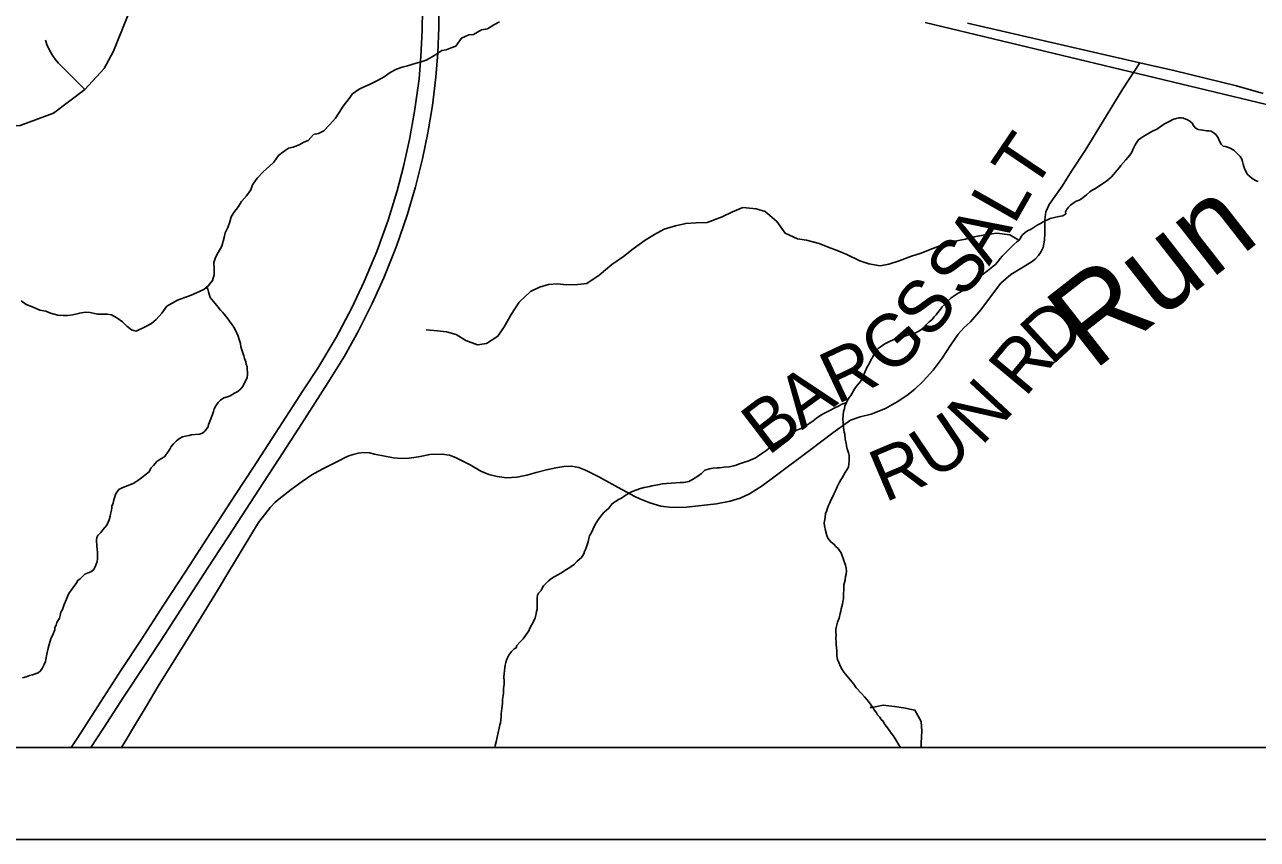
# Model space of a CAD drawing. Extents: x 44.2 to 78.2, y 4.5 to 26.5.
# Drawn here: x 50.4 to 51.74, y 18.501 to 19.388 of the extents above; entities that cross this region are included whole.
import ezdxf

# ---------------------------------------------------------------- set-up
doc = ezdxf.new("R2010")
doc.units = 0
for name, color, linetype in [('GM_X_County_Road', 7, 'Continuous'), ('GM_X_Interstate_Route', 7, 'Continuous'), ('GM_X_Minor_River', 7, 'Continuous'), ('GM_X_Minor_River_Text', 7, 'Continuous'), ('GM_X_Rail_Line', 7, 'Continuous'), ('GM_X_Township_Road', 7, 'Continuous'), ('GM_X_Township_Road_Text', 7, 'Continuous'), ('SH_Cut_Line', 7, 'Continuous'), ('SH_Data', 7, 'Continuous')]:
    doc.layers.add(name, color=color, linetype=linetype)

msp = doc.modelspace()

# ---------------------------------------------------------------- linework, layer by layer
at = {"layer": 'GM_X_County_Road'}
msp.add_lwpolyline([(51.4252, 19.3893), (51.6126, 19.3459), (51.6496, 19.3377), (51.7177, 19.3209), (51.7466, 19.3127)], dxfattribs=at)
at = {"layer": 'GM_X_Interstate_Route'}
for points in [[(50.8508, 19.4119), (50.8504, 19.3846), (50.8492, 19.3569), (50.8471, 19.3303), (50.8433, 19.2997), (50.8383, 19.27), (50.8326, 19.2416), (50.8251, 19.2113), (50.8159, 19.1802), (50.8043, 19.1467), (50.7904, 19.1122), (50.7778, 19.0841), (50.763, 19.0547), (50.7477, 19.027), (50.7297, 18.9981), (50.7013, 18.9539), (50.6765, 18.9156), (50.6541, 18.8811), (50.6273, 18.8398), (50.5992, 18.7969), (50.5752, 18.7598), (50.553, 18.7255), (50.5308, 18.6915), (50.5074, 18.6559), (50.4857, 18.6224), (50.472, 18.6014)], [(50.8327, 19.4043), (50.8323, 19.3811), (50.8309, 19.3529), (50.8288, 19.3288), (50.8239, 19.2932), (50.8185, 19.2627), (50.8119, 19.2333), (50.805, 19.2068), (50.7952, 19.175), (50.783, 19.141), (50.7691, 19.1083), (50.7557, 19.0797), (50.7385, 19.0473), (50.7187, 19.0141), (50.7024, 18.9891), (50.6767, 18.9493), (50.6489, 18.9064), (50.6292, 18.8764), (50.6025, 18.8351), (50.5751, 18.7933), (50.551, 18.7563), (50.5265, 18.7185), (50.5053, 18.686), (50.479, 18.6456), (50.4576, 18.6122), (50.4505, 18.6014)]]:
    msp.add_lwpolyline(points, dxfattribs=at)
at = {"layer": 'GM_X_Minor_River'}
for points in [[(50.7141, 19.2682), (50.7195, 19.2692), (50.7252, 19.2722), (50.7318, 19.2789), (50.738, 19.286), (50.7419, 19.292), (50.7462, 19.2988), (50.7528, 19.3074), (50.7563, 19.3123), (50.7636, 19.3175), (50.7697, 19.3204), (50.775, 19.3226), (50.7835, 19.327), (50.7907, 19.3307), (50.7973, 19.3355), (50.8042, 19.3392), (50.8103, 19.3414), (50.8164, 19.3428), (50.8255, 19.3457), (50.8312, 19.3471), (50.8366, 19.3489), (50.845, 19.3537), (50.8534, 19.3593), (50.8584, 19.3603), (50.8637, 19.3625), (50.8687, 19.3643), (50.8749, 19.3729), (50.883, 19.3766), (50.8879, 19.3769), (50.8967, 19.3821), (50.9032, 19.3831), (50.9101, 19.3875), (50.9162, 19.3905)], [(51.7415, 19.2168), (51.7385, 19.218), (51.7348, 19.2204), (51.7318, 19.2228), (51.7292, 19.2251), (51.7281, 19.2274), (51.7267, 19.2301), (51.7256, 19.2332), (51.7249, 19.2359), (51.7243, 19.2389), (51.7236, 19.2412), (51.7217, 19.2443), (51.7177, 19.2482), (51.7147, 19.2509), (51.7102, 19.2537), (51.7057, 19.2549), (51.7034, 19.2554), (51.7012, 19.2577), (51.699, 19.2616), (51.6979, 19.2646), (51.6957, 19.2677), (51.6935, 19.2697), (51.6901, 19.2717), (51.6875, 19.2721), (51.6852, 19.2722), (51.6811, 19.2727), (51.6761, 19.2736), (51.6728, 19.2755), (51.6709, 19.2779), (51.6695, 19.2806), (51.6669, 19.2825), (51.6646, 19.2841), (51.6601, 19.2857), (51.6579, 19.2862), (51.6552, 19.2862), (51.6521, 19.2856), (51.6487, 19.2845), (51.6452, 19.2827), (51.6422, 19.2813), (51.6395, 19.2798), (51.6348, 19.2765), (51.6317, 19.2743), (51.6256, 19.2715), (51.6171, 19.2664), (51.6136, 19.2642), (51.6113, 19.2624), (51.6093, 19.2597), (51.6077, 19.2568), (51.6057, 19.2534), (51.6037, 19.2481), (51.6017, 19.2455), (51.5974, 19.2407), (51.592, 19.2344), (51.59, 19.2318), (51.5818, 19.2221), (51.5763, 19.2174), (51.5636, 19.209), (51.5609, 19.2075), (51.5582, 19.2057), (51.5547, 19.2024), (51.5493, 19.198), (51.5466, 19.1965), (51.5435, 19.1955), (51.5412, 19.194), (51.5373, 19.1914), (51.535, 19.1892), (51.533, 19.1862), (51.5318, 19.184), (51.5321, 19.1817), (51.529, 19.1795), (51.5245, 19.1789), (51.5153, 19.1768), (51.5076, 19.1732), (51.5045, 19.1714), (51.5011, 19.1696), (51.4945, 19.1652), (51.4906, 19.1634), (51.4879, 19.1616), (51.4852, 19.159), (51.4833, 19.1564), (51.482, 19.1538), (51.4789, 19.1512), (51.4755, 19.1483), (51.4727, 19.1457), (51.4692, 19.142)], [(50.4656, 19.0749), (50.4713, 19.0744), (50.4793, 19.0727), (50.4895, 19.0725), (50.4944, 19.0721), (50.5, 19.0686), (50.5064, 19.0643), (50.5112, 19.0596), (50.5161, 19.0558), (50.521, 19.0541), (50.531, 19.0589), (50.5378, 19.0626), (50.5429, 19.0667), (50.549, 19.0738), (50.5545, 19.0813), (50.566, 19.088), (50.574, 19.0909), (50.5809, 19.0934), (50.5866, 19.096), (50.5946, 19.0996), (50.6, 19.1037), (50.6043, 19.1093), (50.6059, 19.1154), (50.606, 19.1211), (50.6058, 19.1287), (50.6074, 19.1344), (50.6102, 19.1396), (50.6145, 19.1468), (50.6169, 19.1559), (50.6181, 19.1612), (50.6209, 19.1668), (50.6229, 19.1732), (50.6245, 19.1785), (50.6273, 19.1834), (50.6323, 19.1898), (50.6358, 19.1954), (50.6412, 19.2014), (50.6459, 19.2078), (50.6475, 19.2135), (50.6526, 19.2206), (50.6595, 19.2277), (50.6657, 19.2333), (50.6707, 19.2381), (50.6758, 19.2453), (50.6808, 19.249), (50.6869, 19.2531), (50.6919, 19.2545), (50.6984, 19.2567), (50.7034, 19.2596), (50.7083, 19.2614), (50.7141, 19.2682), (50.7153, 19.2685)], [(51.4802, 19.1523), (51.4811, 19.1533), (51.4714, 19.1588), (51.457, 19.1606), (51.4463, 19.1593), (51.4326, 19.1569), (51.4231, 19.1544), (51.4116, 19.152), (51.3982, 19.1481), (51.3848, 19.143), (51.3749, 19.139), (51.3642, 19.1358), (51.3508, 19.1308), (51.3397, 19.1272), (51.3302, 19.1254), (51.318, 19.1276), (51.3082, 19.1308), (51.2939, 19.1376), (51.2834, 19.142), (51.2736, 19.1456), (51.2638, 19.1496), (51.2502, 19.1532), (51.2404, 19.1546), (51.2268, 19.1609), (51.218, 19.1733), (51.2053, 19.1842), (51.1955, 19.1874), (51.181, 19.1888), (51.1696, 19.1841), (51.1584, 19.1786), (51.1423, 19.1725), (51.1302, 19.1719), (51.1188, 19.1714), (51.1077, 19.1689), (51.0955, 19.165), (51.0847, 19.1595), (51.0747, 19.1532), (51.0616, 19.1436), (51.0512, 19.1354), (51.0385, 19.1266), (51.0246, 19.115), (51.0111, 19.1062), (51.0016, 19.1048), (50.989, 19.1047), (50.9792, 19.1057), (50.9696, 19.1051), (50.9597, 19.1022), (50.9501, 19.0975), (50.9377, 19.0859), (50.9291, 19.0724), (50.9212, 19.0589), (50.9146, 19.0487), (50.9022, 19.0406), (50.8923, 19.0393), (50.8795, 19.0441), (50.869, 19.0504), (50.8588, 19.0536), (50.849, 19.0546), (50.8364, 19.0556)], [(51.4692, 19.142), (51.4657, 19.1387), (51.463, 19.1357), (51.461, 19.1335), (51.4587, 19.1305), (51.4555, 19.1268), (51.4532, 19.125), (51.4505, 19.1228), (51.447, 19.1198), (51.4427, 19.1165), (51.44, 19.1143), (51.4377, 19.1121), (51.4338, 19.1092), (51.4307, 19.1066), (51.428, 19.1044), (51.4245, 19.1014), (51.4206, 19.0985), (51.4149, 19.0956), (51.4118, 19.0934), (51.4075, 19.0905), (51.4021, 19.0853), (51.4001, 19.0831), (51.3978, 19.0805), (51.3962, 19.0783), (51.3942, 19.076), (51.3911, 19.072), (51.3888, 19.0697), (51.3864, 19.0664), (51.3837, 19.0642), (51.3813, 19.062), (51.3782, 19.0586), (51.3755, 19.0564), (51.3732, 19.0546), (51.3678, 19.0521), (51.3651, 19.051), (51.3621, 19.0503), (51.3594, 19.0496), (51.3552, 19.0479), (51.3525, 19.0468), (51.346, 19.0454), (51.3437, 19.0444), (51.341, 19.0433), (51.3383, 19.0418), (51.336, 19.0408), (51.3333, 19.0389), (51.3302, 19.0367), (51.3279, 19.0353), (51.3251, 19.0319), (51.3175, 19.0177), (51.316, 19.0155), (51.3151, 19.0129), (51.3119, 19.0054), (51.3087, 18.9994), (51.3044, 18.9942), (51.3028, 18.9919), (51.3012, 18.9893), (51.2985, 18.9841), (51.2965, 18.9819), (51.2945, 18.9785), (51.2933, 18.9755), (51.2917, 18.9729), (51.2913, 18.9698), (51.2904, 18.9668), (51.2899, 18.9631), (51.2898, 18.9577), (51.2901, 18.9555), (51.2901, 18.9528), (51.2904, 18.9494), (51.291, 18.9444), (51.2917, 18.9421), (51.2923, 18.9368), (51.2933, 18.9322), (51.2937, 18.9296), (51.2943, 18.9261), (51.2957, 18.9219), (51.2964, 18.9189), (51.2967, 18.9166), (51.2966, 18.9124), (51.2962, 18.9102), (51.2957, 18.9064), (51.2922, 18.9004), (51.289, 18.8948), (51.2874, 18.8926), (51.2862, 18.8899), (51.2834, 18.8847), (51.2818, 18.8806), (51.2798, 18.8768), (51.2786, 18.8742), (51.277, 18.8712), (51.2754, 18.8674), (51.2741, 18.8644), (51.2729, 18.8618), (51.2721, 18.8592), (51.2709, 18.8558), (51.2704, 18.852), (51.27, 18.8494), (51.2695, 18.8456), (51.2698, 18.8425), (51.2708, 18.8372), (51.2722, 18.8319), (51.2733, 18.8292)], [(50.5961, 19.1007), (50.5988, 19.1014), (50.5998, 19.0968), (50.6005, 19.0945), (50.6015, 19.0907), (50.6052, 19.0864), (50.6085, 19.0826), (50.6104, 19.0802), (50.613, 19.0771), (50.6152, 19.0748), (50.617, 19.0725), (50.62, 19.0686), (50.6225, 19.0651), (50.6247, 19.062), (50.6273, 19.0586), (50.6288, 19.0559), (50.6306, 19.052), (50.632, 19.0486), (50.6327, 19.0463), (50.6345, 19.0409), (50.6351, 19.0371), (50.6365, 19.0329), (50.6372, 19.0306), (50.6383, 19.0275), (50.639, 19.0245), (50.6404, 19.021), (50.6407, 19.0184), (50.6418, 19.0153), (50.6417, 19.0126), (50.6424, 19.0092), (50.6423, 19.0066), (50.6419, 19.0039), (50.6398, 18.999), (50.6367, 18.9938), (50.6347, 18.9912), (50.6316, 18.9886), (50.6281, 18.9868), (50.6235, 18.9839), (50.6204, 18.9828), (50.6166, 18.9818), (50.6128, 18.9793), (50.6104, 18.9767), (50.6077, 18.9729), (50.6061, 18.9696), (50.6052, 18.9669), (50.604, 18.9636), (50.6008, 18.9553), (50.5999, 18.9527), (50.5995, 18.95), (50.5959, 18.9455), (50.5932, 18.9433), (50.5902, 18.9423), (50.581, 18.9414), (50.5787, 18.9407), (50.5749, 18.94), (50.5715, 18.9394), (50.5684, 18.9375), (50.5649, 18.935), (50.5618, 18.9316), (50.5594, 18.9287), (50.5578, 18.9257), (50.5555, 18.9227), (50.5535, 18.9197), (50.5519, 18.9175), (50.5481, 18.9153), (50.5438, 18.9124), (50.5399, 18.9079), (50.5372, 18.905), (50.5352, 18.9012), (50.5305, 18.8976), (50.527, 18.8946), (50.5228, 18.8917), (50.5185, 18.8888), (50.5124, 18.8863), (50.5066, 18.8841), (50.5024, 18.882), (50.4993, 18.8779), (50.4984, 18.8753), (50.4964, 18.8692), (50.496, 18.867), (50.4947, 18.864), (50.4947, 18.8617), (50.4942, 18.8594), (50.4934, 18.8553), (50.4929, 18.853), (50.4917, 18.8489), (50.4909, 18.8466), (50.4893, 18.8432), (50.4869, 18.8403), (50.485, 18.838), (50.4826, 18.8351), (50.4795, 18.8321), (50.4783, 18.8299), (50.4779, 18.8272), (50.4784, 18.82), (50.4787, 18.8173), (50.479, 18.8132), (50.4793, 18.8094), (50.4792, 18.8067), (50.4788, 18.8037), (50.4767, 18.798)], [(50.3961, 19.0871), (50.4017, 19.0832), (50.4092, 19.0804), (50.4164, 19.0772), (50.4228, 19.076), (50.4281, 19.0736), (50.436, 19.0716), (50.4417, 19.0711), (50.447, 19.0714), (50.4523, 19.072), (50.4599, 19.0738), (50.4656, 19.0749)], [(51.2938, 18.9767), (51.288, 18.9745), (51.2856, 18.973), (51.2803, 18.9705), (51.2749, 18.9676), (51.2718, 18.9662), (51.2683, 18.9644), (51.2645, 18.9622), (51.261, 18.9596), (51.2575, 18.9567), (51.2536, 18.9541), (51.2505, 18.9519), (51.2471, 18.9498), (51.2432, 18.948), (51.2398, 18.9465), (51.2371, 18.9451), (51.2348, 18.9436), (51.2317, 18.9418), (51.229, 18.94), (51.2255, 18.9378), (51.2224, 18.9356), (51.2158, 18.9316), (51.212, 18.9291), (51.2096, 18.9268), (51.2058, 18.9239), (51.2027, 18.9217), (51.1969, 18.9177), (51.1942, 18.9159), (51.1896, 18.9141), (51.1873, 18.913), (51.1804, 18.9109), (51.1762, 18.9095), (51.1735, 18.9084), (51.1712, 18.9077), (51.1662, 18.9067), (51.1605, 18.9061), (51.1555, 18.9055), (51.1529, 18.9056), (51.1483, 18.9053), (51.1445, 18.9046), (51.1395, 18.9029), (51.136, 18.8995), (51.1318, 18.8966), (51.126, 18.893), (51.1221, 18.8908), (51.1187, 18.8898), (51.1164, 18.8894), (51.1126, 18.8895), (51.1084, 18.8893), (51.1035, 18.889), (51.0978, 18.8884), (51.0936, 18.8881), (51.0886, 18.8871), (51.0863, 18.8868), (51.0821, 18.8858), (51.0798, 18.8851), (51.0737, 18.8841), (51.0695, 18.8831), (51.0645, 18.8813), (51.0615, 18.8802), (51.0592, 18.8792), (51.0565, 18.8777), (51.053, 18.8755), (51.0491, 18.8726), (51.0457, 18.8712), (51.043, 18.8694), (51.0406, 18.8679), (51.0383, 18.8661), (51.0352, 18.8616), (51.0301, 18.8572), (51.0278, 18.8546), (51.0242, 18.8501), (51.0223, 18.8467), (51.0203, 18.8438), (51.0179, 18.8385), (51.0163, 18.8351), (51.0143, 18.8314), (51.0134, 18.8288), (51.013, 18.8265), (51.0122, 18.8239), (51.0109, 18.8197), (51.0097, 18.8167), (51.0089, 18.8145), (51.0081, 18.8118), (51.0053, 18.8081), (51.0007, 18.8041), (50.9979, 18.8007), (50.9941, 18.7982), (50.9917, 18.7963), (50.9886, 18.7945), (50.9863, 18.7931), (50.9836, 18.7912), (50.9759, 18.7869), (50.9728, 18.7851), (50.9697, 18.7825), (50.9662, 18.7795), (50.9643, 18.7773)], [(51.2733, 18.8292), (51.2766, 18.8249), (51.2803, 18.8222), (51.2821, 18.8198), (51.2844, 18.8179), (51.2862, 18.8156), (51.288, 18.8129), (51.2912, 18.8037), (51.2926, 18.7998), (51.2933, 18.7964), (51.2936, 18.793), (51.2931, 18.79), (51.2927, 18.7873), (51.2922, 18.7832), (51.2906, 18.7783), (51.2902, 18.7631), (51.2897, 18.7601), (51.2893, 18.7574), (51.288, 18.7521), (51.2876, 18.7495), (51.2867, 18.7469), (51.2855, 18.742), (51.2838, 18.7375), (51.2826, 18.7333), (51.2821, 18.7299), (51.282, 18.7269), (51.2823, 18.7235), (51.2822, 18.7201), (51.2825, 18.7159), (51.2825, 18.7132), (51.2828, 18.7102), (51.283, 18.7064), (51.283, 18.7037), (51.2833, 18.7011), (51.2839, 18.6972), (51.2854, 18.6938), (51.2872, 18.6896), (51.289, 18.6861), (51.2908, 18.6834), (51.2927, 18.6811), (51.3015, 18.6702), (51.3041, 18.6664), (51.31, 18.6601), (51.3133, 18.6563), (51.3155, 18.6539), (51.3177, 18.6512), (51.3203, 18.6473), (51.3225, 18.6446), (51.3236, 18.6423), (51.3262, 18.6392), (51.3272, 18.6369), (51.3298, 18.6342), (51.3313, 18.6319), (51.3335, 18.6299), (51.3346, 18.6276), (51.3368, 18.6245), (51.3405, 18.6199), (51.3423, 18.6168), (51.3445, 18.6145), (51.3474, 18.6098), (51.3507, 18.6044), (51.3525, 18.6014)], [(50.4767, 18.798), (50.4747, 18.7947), (50.472, 18.7925), (50.469, 18.7914), (50.4655, 18.79), (50.4601, 18.7848), (50.4577, 18.783), (50.4561, 18.7796), (50.4534, 18.7763), (50.451, 18.7729), (50.4487, 18.7699), (50.4467, 18.7666), (50.4455, 18.7628), (50.443, 18.7568), (50.441, 18.7515), (50.4394, 18.7486), (50.4385, 18.7448), (50.4377, 18.7421), (50.4349, 18.7373), (50.4341, 18.7343), (50.4329, 18.7317), (50.4328, 18.7294), (50.4308, 18.7249), (50.4284, 18.7196), (50.4267, 18.7132), (50.4251, 18.708), (50.4242, 18.703), (50.4229, 18.697), (50.4224, 18.6947), (50.4208, 18.691), (50.4188, 18.6872), (50.4173, 18.6846), (50.4145, 18.6824), (50.4084, 18.6803), (50.405, 18.6796), (50.4015, 18.6782), (50.3977, 18.6772)], [(50.9643, 18.7773), (50.9627, 18.7747), (50.9615, 18.7721), (50.9587, 18.7691), (50.9576, 18.7669), (50.9571, 18.7642), (50.9574, 18.7604), (50.9572, 18.7517), (50.9567, 18.7491), (50.9559, 18.7453), (50.955, 18.7423), (50.9534, 18.7385), (50.9494, 18.731), (50.9482, 18.7284), (50.9419, 18.7195), (50.9384, 18.7158), (50.9353, 18.7124), (50.9345, 18.7098), (50.9321, 18.7087), (50.9294, 18.7058), (50.9266, 18.7017), (50.9243, 18.6975), (50.923, 18.6938), (50.9226, 18.6908), (50.9221, 18.6885), (50.9217, 18.6847), (50.9212, 18.6817), (50.9211, 18.6779), (50.9214, 18.6737), (50.9213, 18.6699), (50.9208, 18.6658), (50.9207, 18.6601), (50.9202, 18.6578), (50.9197, 18.6537), (50.9196, 18.6491), (50.9187, 18.6438), (50.9182, 18.6378), (50.9181, 18.6347), (50.9176, 18.6313), (50.9172, 18.6283), (50.9167, 18.626), (50.9159, 18.6223), (50.915, 18.6177), (50.9125, 18.6076), (50.9116, 18.6034), (50.9113, 18.6014)], [(51.3212, 18.6462), (51.3198, 18.6446), (51.3336, 18.6474), (51.3457, 18.646), (51.3555, 18.6443), (51.368, 18.6421), (51.375, 18.6295), (51.3755, 18.6192), (51.3749, 18.6063), (51.3748, 18.6014)]]:
    msp.add_lwpolyline(points, dxfattribs=at)
at = {"layer": 'GM_X_Rail_Line'}
for points in [[(51.3792, 19.39), (51.8335, 19.2809)], [(48.642, 18.6014), (53.1359, 18.6014)]]:
    msp.add_lwpolyline(points, dxfattribs=at)
at = {"layer": 'GM_X_Township_Road'}
for points in [[(50.2848, 19.2628), (50.3573, 19.2758), (50.3951, 19.2779), (50.4311, 19.2914), (50.4652, 19.3172), (50.4862, 19.3399), (50.4964, 19.3587), (50.5121, 19.3975), (50.5189, 19.4153), (50.538, 19.4668), (50.5494, 19.4963), (50.5609, 19.5278), (50.566, 19.5402), (50.5677, 19.5516), (50.5613, 19.5722), (50.5258, 19.6879)], [(50.4652, 19.3172), (50.4367, 19.3456), (50.4344, 19.3483), (50.4319, 19.3515), (50.4297, 19.3548), (50.4279, 19.3579), (50.4256, 19.3626), (50.4242, 19.366), (50.4226, 19.3706)], [(50.5053, 18.6014), (50.5092, 18.608), (50.5184, 18.6231), (50.533, 18.6478), (50.545, 18.6681), (50.5834, 18.7298), (50.6095, 18.7722), (50.6221, 18.7928), (50.6292, 18.8046), (50.6541, 18.8461), (50.6671, 18.8629), (50.6719, 18.8678), (50.6781, 18.8729), (50.6899, 18.8818), (50.7018, 18.8905), (50.7123, 18.8978), (50.7187, 18.9017), (50.7256, 18.9052), (50.7407, 18.9129), (50.7484, 18.9168), (50.7526, 18.9187), (50.757, 18.9202), (50.7628, 18.9216), (50.7684, 18.9221), (50.775, 18.9217), (50.7804, 18.9205), (50.7917, 18.9183), (50.8011, 18.9165), (50.8096, 18.9157), (50.818, 18.916), (50.8283, 18.9176), (50.8404, 18.9199), (50.8536, 18.9205), (50.8618, 18.9193), (50.8685, 18.9167), (50.8843, 18.9088), (50.8959, 18.902), (50.9046, 18.8983), (50.9136, 18.8962), (50.9239, 18.8948), (50.935, 18.8954), (50.9461, 18.8975), (50.9563, 18.9004), (50.9674, 18.9035), (50.9777, 18.9056), (50.9864, 18.9071), (50.9947, 18.9073), (51.0025, 18.9058), (51.0097, 18.9031), (51.0249, 18.8955), (51.0453, 18.8842), (51.0635, 18.8744), (51.0688, 18.8719), (51.0797, 18.8673), (51.0916, 18.864), (51.1038, 18.8625), (51.1198, 18.8629), (51.1522, 18.8665), (51.1673, 18.8691), (51.1779, 18.8725), (51.1883, 18.8773), (51.2018, 18.8858), (51.2145, 18.8953), (51.2549, 18.9254), (51.2789, 18.9436), (51.2979, 18.9573), (51.3085, 18.961), (51.3205, 18.964), (51.3362, 18.9702), (51.3486, 18.9772), (51.3591, 18.9842), (51.3678, 18.9912), (51.3769, 18.9998), (51.3879, 19.0116), (51.3977, 19.0247), (51.407, 19.0392), (51.4149, 19.0508), (51.4214, 19.0577), (51.4285, 19.0642), (51.4398, 19.0774), (51.4523, 19.0943), (51.4615, 19.1065), (51.4725, 19.1157), (51.4944, 19.1293), (51.4988, 19.1326), (51.5025, 19.1364), (51.5055, 19.1408), (51.5075, 19.1453), (51.509, 19.1532), (51.5092, 19.1608), (51.5094, 19.1754), (51.5105, 19.1841), (51.5142, 19.1919), (51.5281, 19.212), (51.5385, 19.2282), (51.5531, 19.2508), (51.5811, 19.2964), (51.5941, 19.3176), (51.6126, 19.3459)]]:
    msp.add_lwpolyline(points, dxfattribs=at)
at = {"layer": 'SH_Cut_Line'}
msp.add_lwpolyline([(48.642, 18.6014), (53.1359, 18.6014), (53.1359, 25.4014)], dxfattribs=at)
at = {"layer": 'SH_Data'}
for p, q in [((46.3359, 18.6014), (53.1359, 18.6014)), ((46.2359, 18.5014), (53.2359, 18.5014))]:
    msp.add_line(p, q, dxfattribs=at)

# ---------------------------------------------------------------- texts
at = {"layer": 'GM_X_Minor_River_Text'}
msp.add_text('Run', height=0.09471, rotation=38.0042, dxfattribs=at).set_placement((51.5622, 19.0103))
at = {"layer": 'GM_X_Township_Road_Text'}
for s, rotation, p in [('T', 55.9854, (51.4961, 19.2047)), ('L', 60.4327, (51.4758, 19.1687)), ('A', 58.5559, (51.4487, 19.1243)), ('S', 51.6251, (51.4206, 19.0881)), ('S', 50.8026, (51.3844, 19.044)), ('D', 42.8074, (51.5164, 19.0156)), ('G', 41.3258, (51.3398, 19.0036)), ('R', 50.2454, (51.4879, 18.9812)), ('R', 25.2628, (51.2831, 18.9741)), ('A', 36.1712, (51.2452, 18.9461)), ('N', 47.1108, (51.4404, 18.9283)), ('B', 37.3742, (51.2083, 18.9179)), ('U', 33.937, (51.3883, 18.8913)), ('R', 23.0597, (51.3352, 18.8675))]:
    msp.add_text(s, height=0.0568, rotation=rotation, dxfattribs=at).set_placement(p)

doc.saveas('drawing.dxf')
